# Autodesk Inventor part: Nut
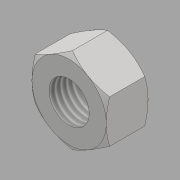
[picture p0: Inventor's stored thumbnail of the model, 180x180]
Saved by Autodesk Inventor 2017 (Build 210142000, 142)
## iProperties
Created: 2016-05
Part Number: Nut
Material: Generic
Document SubType Name: Modeling
Designer: CADCIM
Density: 1 g/cm^3
Appearance: Default
Author: CADCIM
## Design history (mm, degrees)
sketch "Sketch1"
  geometry: L1 (9.6, -5.543)-(0, -11.085); L2 (0, -11.085)-(-9.6, -5.543); L3 (-9.6, -5.543)-(-9.6, 5.543); L4 (-9.6, 5.543)-(0, 11.085); L5 (0, 11.085)-(9.6, 5.543); L6 (9.6, 5.543)-(9.6, -5.543); 2 further points
  constraints: 12 end point, 1 coincident, 1 vertical alignment, 13 other
  dimensions: "d0" = 19.2 distance between parallel lines of L3 L6
extrude "Extrusion1" new body sketch "Sketch1" distance "d1" = 10.8; taper "d2" = 0 deg
sketch "Sketch2"
  geometry: L1 (0, 11.085)-(-9.6, 5.543) reference; C1 r 9.6 at (0, 0); 1 further point
  constraints: 1 centre point, 1 coincident, 1 tangent
extrude "Extrusion2" sketch "Sketch2" distance "d3" = 10.8; taper "d4" = 60 deg
workplane "Work Plane1"
sketch "Sketch3"
  geometry: L1 (0, -11.085)-(9.6, -5.543) reference; C1 r 9.6 at (0, 0); 1 further point
  constraints: 1 centre point, 1 coincident, 1 tangent
extrude "Extrusion3" sketch "Sketch3" distance "d5" = 10.8; taper "d6" = 60 deg
sketch "Sketch4"
  geometry: 1 further point
hole "Hole1" diameter "d9" = 10.376; stored, may be unused: countersink angle "d13" = 90 deg, drill point angle "d15" = 118 deg; dims "d7" = 10, "d8" = 10, "d10" = 24, "d11" = 4, "d12" = 2, "d14" = 31.3
body "Solid1"
